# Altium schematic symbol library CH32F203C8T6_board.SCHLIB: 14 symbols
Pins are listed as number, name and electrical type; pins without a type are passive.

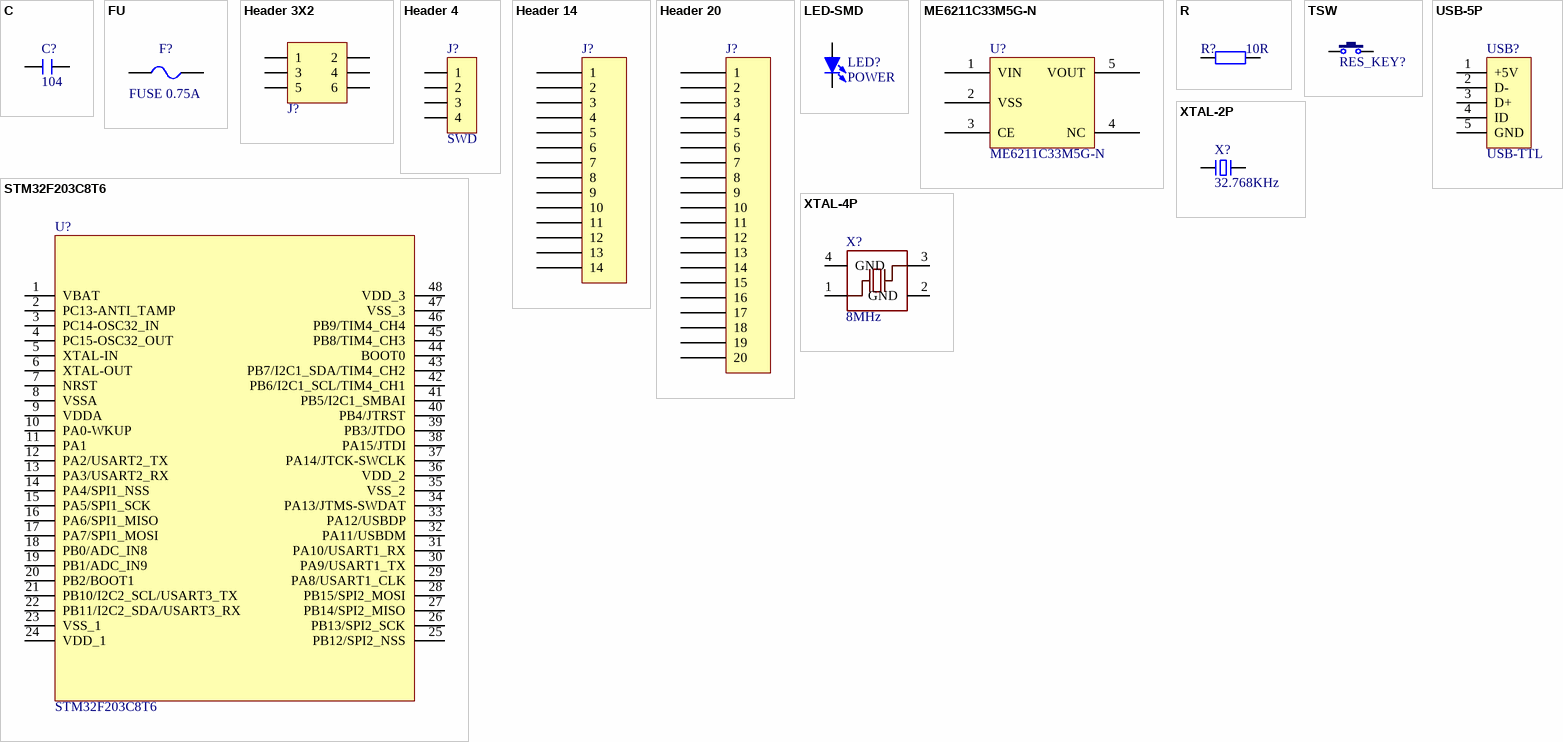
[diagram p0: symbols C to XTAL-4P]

## C
designator C?, comment 104
无极性贴片电容; 版权归属: 源创客; 材质: X7R
footprint C 0603 (无极性贴片电容)
pins: 1, 2

## FU
designator F?, comment FUSE 0.75A
贴片保险丝; 版权归属: 源创客
footprint FU 0805 (贴片保险丝)
footprint FU 0612 (贴片保险丝)
footprint FU 0805 (贴片保险丝)
pins: 1, 2

## Header 3X2
designator J?  (value not drawn)
3*2P接插件; BOM名称: 5*2P接插件; 版权归属: 源创客
footprint IDE3X2-2.54
pins: 1, 2, 3, 4, 5, 6

## Header 4
designator J?, comment SWD
4P接插件; 版权归属: 源创客
footprint HDR1X4 (Connector; Header; 4 Position)
pins: 1, 2, 3, 4

## Header 14
designator J?, comment 14 pin  (value not drawn)
14pin 排针
footprint Header-14-2.54 (header 14 pin)
pins: 1, 2, 3, 4, 5, 6, 7, 8, 9, 10, 11, 12, 13, 14

## Header 20
designator J?, comment 20 pin  (value not drawn)
20pin 排针
footprint Header-20-2.54 (header pin)
pins: 1, 2, 3, 4, 5, 6, 7, 8, 9, 10, 11, 12, 13, 14, 15, 16, 17, 18, 19, 20

## LED-SMD
designator LED?, comment POWER
贴片LED; 版权归属: 源创客
footprint LED0805
pins: 1 A, 2 K

## ME6211C33M5G-N
designator U?
稳压芯片
footprint SOT23-5
pins: 1 VIN, 2 VSS, 3 CE, 4 NC, 5 VOUT

## R
designator R?, comment 10R
贴片电阻; 版权归属: 源创客
footprint R0603
pins: 1, 2

## STM32F203C8T6
designator U?
footprint LQFP48
pins: 1 VBAT, 2 PC13-ANTI_TAMP, 3 PC14-OSC32_IN, 4 PC15-OSC32_OUT, 5 XTAL-IN, 6 XTAL-OUT, 7 NRST, 8 VSSA, 9 VDDA, 10 PA0-WKUP, 11 PA1, 12 PA2/USART2_TX, 13 PA3/USART2_RX, 14 PA4/SPI1_NSS, 15 PA5/SPI1_SCK, 16 PA6/SPI1_MISO, 17 PA7/SPI1_MOSI, 18 PB0/ADC_IN8, 19 PB1/ADC_IN9, 20 PB2/BOOT1, 21 PB10/I2C2_SCL/USART3_TX, 22 PB11/I2C2_SDA/USART3_RX, 23 VSS_1, 24 VDD_1, 25 PB12/SPI2_NSS, 26 PB13/SPI2_SCK, 27 PB14/SPI2_MISO, 28 PB15/SPI2_MOSI, 29 PA8/USART1_CLK, 30 PA9/USART1_TX, 31 PA10/USART1_RX, 32 PA11/USBDM, 33 PA12/USBDP, 34 PA13/JTMS-SWDAT, 35 VSS_2, 36 VDD_2, 37 PA14/JTCK-SWCLK, 38 PA15/JTDI, 39 PB3/JTDO, 40 PB4/JTRST, 41 PB5/I2C1_SMBAI, 42 PB6/I2C1_SCL/TIM4_CH1, 43 PB7/I2C1_SDA/TIM4_CH2, 44 BOOT0, 45 PB8/TIM4_CH3, 46 PB9/TIM4_CH4, 47 VSS_3, 48 VDD_3

## TSW
designator RES_KEY?, comment 3x6x5  (value not drawn)
轻触开关; BOM名称: 3x6轻触开关; 版权归属: 源创客
footprint TSW SMD-3*4*2.5 (3*4*2.5mm)
pins: 1, 2

## USB-5P
designator USB?, comment USB-TTL
微型USB母座; 版权归属: 源创客
footprint USB_T
footprint Micro_USB2 (Micro_USB Dock 5 Pin)
pins: 1 +5V, 2 D-, 3 D+, 4 ID, 5 GND

## XTAL-2P
designator X?, comment 32.768KHz
2脚无源脚晶振; 版权归属: 源创客; 负载电容: CL20pF
footprint 49SMD
footprint OSC 3215-2P (3.2*1.5*0.6mm(长宽高))
pins: 1, 2

## XTAL-4P
designator X?, comment 8MHz
4脚无源脚晶振; BOM名称: 2脚无源脚晶振; 版权归属: 源创客; 负载电容: CL20pF
footprint CRYSTAL-SMD_4P-L3.2-W2.5-BL-1
pins: 1, 2 GND, 3, 4 GND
